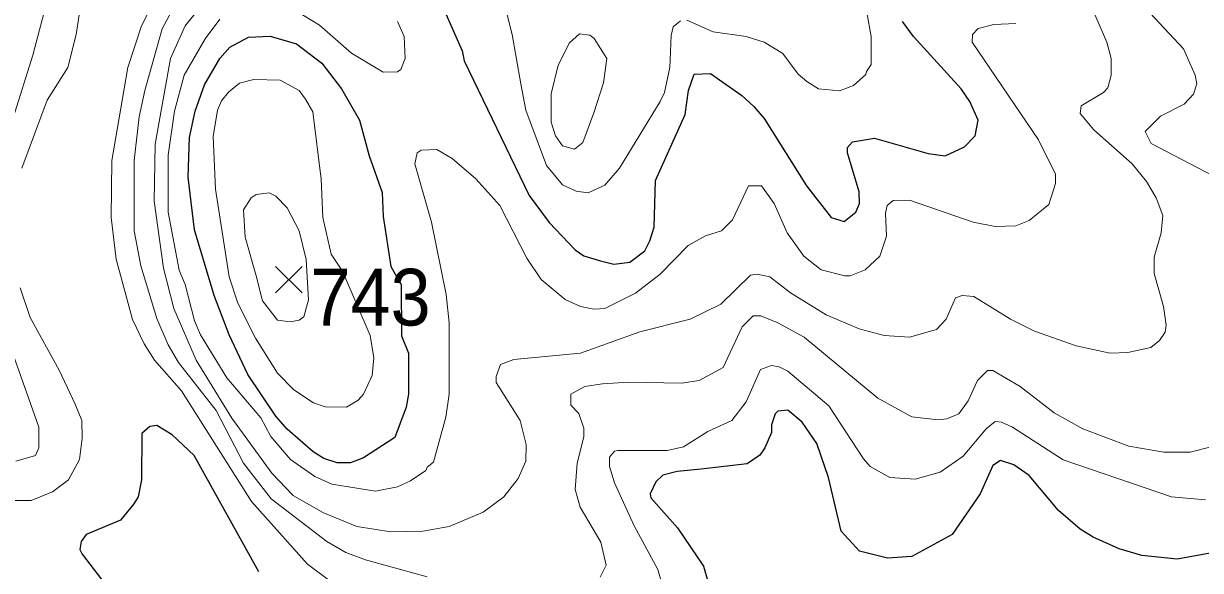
# Model space of a CAD drawing. Extents: x 423 to 448.8, y 7456.3 to 7484.
# Drawn here: x 438.652 to 440.312, y 7468.444 to 7469.215 of the extents above; entities that cross this region are included whole.
import ezdxf
from ezdxf.enums import TextEntityAlignment as Align

# ---------------------------------------------------------------- set-up
doc = ezdxf.new("R2010")
doc.units = 0
doc.header["$LTSCALE"] = 0.032
for name, color, linetype, lineweight in [('1', 7, 'Continuous', 25), ('2', 7, 'Continuous', 13), ('21', 7, 'Continuous', 25)]:
    doc.layers.add(name, color=color, linetype=linetype, lineweight=lineweight)
doc.layers.add('61', color=7, linetype='Continuous')

msp = doc.modelspace()

# ---------------------------------------------------------------- linework, layer by layer
at = {"layer": '1'}
for points in [[(439.2365, 7469.2538), (439.2705, 7469.1764), (439.2736, 7469.1625), (439.3649, 7468.9723), (439.3935, 7468.9343), (439.4299, 7468.8957), (439.4423, 7468.8872), (439.4659, 7468.8804), (439.4844, 7468.8756), (439.5071, 7468.8784), (439.5284, 7468.8945), (439.5355, 7468.9087), (439.5414, 7468.9277), (439.5432, 7468.9938), (439.5853, 7469.0867), (439.59, 7469.1208), (439.5977, 7469.1439), (439.6209, 7469.1447), (439.665, 7469.1138), (439.682, 7469.0983), (439.6967, 7469.0813), (439.7563, 7468.9862), (439.7911, 7468.9413), (439.8096, 7468.9359), (439.8259, 7468.949), (439.8313, 7468.9614), (439.8305, 7468.9776), (439.8143, 7469.0326), (439.8143, 7469.0403), (439.8213, 7469.048), (439.8522, 7469.0534), (439.928, 7469.0318), (439.952, 7469.0287), (439.979, 7469.0411), (439.9945, 7469.0565), (439.9984, 7469.0789), (439.9868, 7469.1053), (439.9744, 7469.1231), (439.9071, 7469.1966), (439.8916, 7469.2182)], [(440.3782, 7468.4772), (440.2792, 7468.4594), (440.2296, 7468.4648), (440.1972, 7468.4741), (440.1608, 7468.4904), (440.1422, 7468.502), (440.112, 7468.5283), (440.0703, 7468.5777), (440.0487, 7468.5925), (440.0301, 7468.5986), (440.0193, 7468.5917), (440.0014, 7468.5515), (439.962, 7468.4942), (439.9048, 7468.4633), (439.8708, 7468.461), (439.8313, 7468.471), (439.805, 7468.4989), (439.7872, 7468.5747), (439.771, 7468.6227), (439.7501, 7468.6528), (439.73, 7468.6698), (439.716, 7468.6682), (439.7122, 7468.6644), (439.7068, 7468.6489), (439.7068, 7468.6381), (439.6975, 7468.6165), (439.6905, 7468.6064), (439.6728, 7468.594), (439.6078, 7468.5863), (439.5738, 7468.5832), (439.5536, 7468.5778), (439.5436, 7468.5685), (439.5358, 7468.5515), (439.5366, 7468.5461)], [(438.9836, 7468.4417), (438.8923, 7468.6056), (438.8614, 7468.635), (438.8397, 7468.6481), (438.8297, 7468.6466), (438.8188, 7468.6366), (438.8181, 7468.5716), (438.8134, 7468.5476), (438.8072, 7468.5376), (438.7887, 7468.5143), (438.74, 7468.4942), (438.733, 7468.4842), (438.7314, 7468.4733), (438.7345, 7468.4664), (438.7732, 7468.4161)], [(439.5366, 7468.5461), (439.5745, 7468.5035), (439.6109, 7468.4494), (439.6202, 7468.4169)]]:
    msp.add_lwpolyline(points, dxfattribs=at)
msp.add_lwpolyline([(439.1392, 7469.0285), (439.1575, 7468.9768), (439.1589, 7468.9428), (439.17, 7468.8725), (439.1844, 7468.8468), (439.1851, 7468.7747), (439.195, 7468.7503), (439.1947, 7468.6923), (439.1917, 7468.6737), (439.1754, 7468.6311), (439.1313, 7468.6025), (439.1128, 7468.5956), (439.0942, 7468.5956), (439.0756, 7468.6017), (439.0602, 7468.611), (439.0238, 7468.6427), (439.0075, 7468.6613), (438.9681, 7468.7201), (438.9418, 7468.7758), (438.9209, 7468.8315), (438.8931, 7468.9243), (438.8838, 7468.9986), (438.8861, 7469.0542), (438.8938, 7469.0914), (438.907, 7469.1285), (438.9287, 7469.1656), (438.9426, 7469.1818), (438.9689, 7469.1958), (438.9998, 7469.1973), (439.037, 7469.1865), (439.0725, 7469.1594), (439.1004, 7469.1231), (439.1259, 7469.079)], close=True, dxfattribs=at)
at = {"layer": '2'}
for points in [[(438.6286, 7469.7906), (438.6804, 7469.6343), (438.6858, 7469.6111), (438.6982, 7469.5059), (438.7051, 7469.4688), (438.7353, 7469.3621), (438.7415, 7469.3157), (438.7384, 7469.2801), (438.726, 7469.1997), (438.7144, 7469.1532), (438.685, 7469.1068), (438.6494, 7469.0109)], [(438.6371, 7469.0821), (438.6649, 7469.1703), (438.6881, 7469.2584), (438.6974, 7469.3172), (438.6889, 7469.3745), (438.6843, 7469.4348), (438.6719, 7469.5075), (438.6441, 7469.5957)], [(439.1135, 7468.4068), (439.0524, 7468.4524), (438.9735, 7468.5407), (438.8745, 7468.6969), (438.8366, 7468.7402), (438.8219, 7468.7634), (438.8057, 7468.7975), (438.7825, 7468.8825), (438.7755, 7468.9413), (438.7763, 7469.0218), (438.7987, 7469.1532), (438.8181, 7469.212), (438.8366, 7469.2476), (438.8498, 7469.2832), (438.8591, 7469.3172), (438.8761, 7469.4255), (438.8761, 7469.4611), (438.8854, 7469.5183), (438.8885, 7469.5647)], [(439.5784, 7469.219), (439.5683, 7469.2105), (439.5652, 7469.1981), (439.5637, 7469.1532), (439.5559, 7469.1177), (439.5498, 7469.1053), (439.4925, 7469.0109), (439.4716, 7468.9869), (439.4485, 7468.9761), (439.4314, 7468.9784), (439.4121, 7468.9877), (439.3897, 7469.0148), (439.3603, 7469.0929), (439.3533, 7469.13), (439.3409, 7469.1997), (439.3231, 7469.2708)], [(440.2072, 7469.2662), (440.2884, 7469.1795), (440.3046, 7469.1424), (440.307, 7469.13), (440.3023, 7469.1153), (440.2892, 7469.1014), (440.2559, 7469.0844), (440.2343, 7469.0627), (440.2428, 7469.0457), (440.341, 7468.9947)], [(439.0795, 7468.4842), (439.0013, 7468.5445), (438.9619, 7468.5948), (438.9233, 7468.6691), (438.8706, 7468.7371), (438.8559, 7468.7619), (438.8397, 7468.799), (438.8173, 7468.8733), (438.808, 7468.9228), (438.808, 7469.0218), (438.815, 7469.0836), (438.8227, 7469.1208), (438.8474, 7469.2074), (438.8737, 7469.2569)], [(438.9062, 7469.2445), (438.8799, 7469.212), (438.8591, 7469.1656), (438.8374, 7469.045), (438.8359, 7468.9645), (438.849, 7468.8702), (438.8637, 7468.8129), (438.8745, 7468.7882), (438.8954, 7468.7402), (438.9457, 7468.6582), (439.0022, 7468.5809), (439.0323, 7468.5492), (439.0741, 7468.5252), (439.1221, 7468.5058), (439.17, 7468.4981), (439.2149, 7468.4989), (439.252, 7468.5058), (439.3, 7468.5259), (439.3293, 7468.5476), (439.3494, 7468.5731), (439.3603, 7468.5979), (439.361, 7468.6211), (439.3525, 7468.6551), (439.3185, 7468.7085), (439.3185, 7468.717), (439.3247, 7468.734), (439.3433, 7468.741), (439.4376, 7468.7502), (439.5212, 7468.7804), (439.5923, 7468.7982), (439.6356, 7468.8191), (439.6774, 7468.8601), (439.6867, 7468.8616), (439.7044, 7468.8578), (439.7338, 7468.8353), (439.7841, 7468.8044), (439.8305, 7468.7843), (439.8661, 7468.775), (439.9017, 7468.7727), (439.9396, 7468.7835)], [(439.1793, 7469.2182), (439.1885, 7469.1966), (439.1901, 7469.1656), (439.1839, 7469.1501), (439.1792, 7469.1471), (439.1591, 7469.1463), (439.1143, 7469.1733), (439.0694, 7469.2128), (439.0261, 7469.2391)], [(439.8414, 7469.2306), (439.8476, 7469.1966), (439.8476, 7469.1571), (439.841, 7469.1473), (439.8398, 7469.1432), (439.8228, 7469.1277), (439.8027, 7469.12), (439.7733, 7469.123), (439.757, 7469.1331), (439.7447, 7469.1439), (439.723, 7469.1726), (439.6967, 7469.1888), (439.6712, 7469.1966), (439.6248, 7469.2035), (439.5877, 7469.2197)], [(439.9396, 7468.7835), (439.9535, 7468.7982), (439.9667, 7468.8283), (439.9759, 7468.8314), (439.9922, 7468.8299), (440.044, 7468.7982), (440.0781, 7468.7812), (440.1368, 7468.7603), (440.1848, 7468.7502), (440.2095, 7468.751), (440.242, 7468.758), (440.2544, 7468.7681), (440.2621, 7468.7796), (440.2637, 7468.7897), (440.2598, 7468.816), (440.2467, 7468.8624), (440.2467, 7468.8856), (440.2567, 7468.9197), (440.259, 7468.9444), (440.2497, 7468.9692), (440.2358, 7468.9924), (440.2157, 7469.0171), (440.1616, 7469.065), (440.1422, 7469.0883), (440.1438, 7469.0991), (440.1755, 7469.1177), (440.1816, 7469.1246), (440.1863, 7469.1424), (440.1863, 7469.1656), (440.1801, 7469.1888), (440.16, 7469.2352)], [(438.9287, 7469.2213), (438.9078, 7469.1935), (438.8784, 7469.1424), (438.8645, 7469.0914), (438.856, 7469.0295), (438.856, 7468.9491), (438.8714, 7468.8671), (438.8799, 7468.847), (438.8931, 7468.7959), (438.9016, 7468.7758), (438.9387, 7468.7154), (438.9867, 7468.659), (439.0006, 7468.6327), (439.0285, 7468.6002), (439.0625, 7468.5762), (439.0865, 7468.5654), (439.1484, 7468.5553), (439.1793, 7468.5615), (439.1978, 7468.57), (439.2195, 7468.5847)], [(439.2195, 7468.5847), (439.221, 7468.5894), (439.2303, 7468.5963), (439.2473, 7468.6598), (439.252, 7468.6923), (439.252, 7468.7309), (439.252, 7468.7928), (439.2481, 7468.833), (439.2272, 7468.9351), (439.204, 7469.0171), (439.2071, 7469.0325), (439.2125, 7469.0364), (439.2349, 7469.0372), (439.2566, 7469.0248), (439.2899, 7468.9962), (439.3239, 7468.9583), (439.3618, 7468.8841), (439.3819, 7468.8539), (439.416, 7468.826), (439.4376, 7468.816), (439.4562, 7468.8121), (439.4717, 7468.8129), (439.515, 7468.8346), (439.5498, 7468.8616), (439.5892, 7468.9018), (439.614, 7468.9158), (439.6364, 7468.9227), (439.6518, 7468.9382), (439.6743, 7468.9861), (439.6928, 7468.9862), (439.7106, 7468.9614), (439.7292, 7468.9197), (439.7524, 7468.8871), (439.7771, 7468.8678), (439.8104, 7468.8593), (439.8181, 7468.8593), (439.839, 7468.8678), (439.8599, 7468.8871), (439.8692, 7468.915), (439.8676, 7468.9475), (439.87, 7468.9583), (439.8785, 7468.9653), (439.9017, 7468.9661), (439.9914, 7468.9351), (440.0224, 7468.9289), (440.0518, 7468.9297), (440.0703, 7468.9374), (440.0982, 7468.9598), (440.1074, 7468.9893), (440.1074, 7469.0024), (440.0835, 7469.0511), (439.9899, 7469.1888), (439.9906, 7469.1997), (439.9984, 7469.2081), (440.0208, 7469.2136), (440.0518, 7469.2151)], [(438.6471, 7468.8423), (438.6611, 7468.8005), (438.702, 7468.7263), (438.7245, 7468.6783), (438.7338, 7468.6551), (438.7345, 7468.6304), (438.7307, 7468.6002), (438.7152, 7468.5716), (438.6928, 7468.5546), (438.6626, 7468.5422), (438.6379, 7468.5422)], [(440.3271, 7468.618), (440.2977, 7468.6102), (440.2606, 7468.6102), (440.2111, 7468.6188), (440.1461, 7468.6435), (440.1059, 7468.6659), (440.0579, 7468.7031), (440.0193, 7468.7255), (440.0115, 7468.7255), (439.9976, 7468.7116), (439.9844, 7468.683), (439.9713, 7468.6644), (439.9543, 7468.6574), (439.9419, 7468.6559), (439.9048, 7468.6605), (439.8568, 7468.6868), (439.7532, 7468.7727), (439.7161, 7468.7928), (439.6921, 7468.8028), (439.6812, 7468.8028), (439.6658, 7468.7874), (439.6387, 7468.7301), (439.6047, 7468.7116), (439.5799, 7468.7077), (439.5057, 7468.7092), (439.4686, 7468.7069), (439.4438, 7468.7031), (439.4237, 7468.6922), (439.4237, 7468.6767), (439.4353, 7468.6652), (439.4423, 7468.6443), (439.4423, 7468.6319), (439.433, 7468.5948), (439.4299, 7468.5577), (439.4368, 7468.5329), (439.4662, 7468.4834), (439.4739, 7468.4509), (439.4654, 7468.4339)], [(438.641, 7468.5979), (438.6688, 7468.6056), (438.6734, 7468.6165), (438.6734, 7468.6459), (438.6371, 7468.748)], [(440.3194, 7468.543), (440.2714, 7468.5476), (440.1183, 7468.5994), (440.0471, 7468.6458), (440.0316, 7468.6528), (440.0224, 7468.6535), (440.0099, 7468.6435), (439.9775, 7468.6048), (439.945, 7468.5824), (439.9094, 7468.5723), (439.8739, 7468.5747), (439.846, 7468.5901), (439.8367, 7468.601), (439.788, 7468.676), (439.73, 7468.7247), (439.7176, 7468.7309), (439.7068, 7468.7325), (439.6913, 7468.727), (439.6712, 7468.6814), (439.6511, 7468.6551), (439.6171, 7468.6396), (439.583, 7468.618), (439.5598, 7468.6126), (439.4902, 7468.6126), (439.4855, 7468.6118), (439.4786, 7468.6033), (439.4786, 7468.5902), (439.4855, 7468.567), (439.5134, 7468.5066), (439.5467, 7468.4448), (439.5567, 7468.4107)], [(439.2211, 7468.4347), (439.1344, 7468.4587), (439.1066, 7468.4687), (439.0795, 7468.4842)]]:
    msp.add_lwpolyline(points, dxfattribs=at)
for points in [[(439.4565, 7469.089), (439.4701, 7469.1316), (439.4747, 7469.1656), (439.4569, 7469.1942), (439.4507, 7469.1989), (439.436, 7469.2004), (439.4222, 7469.188), (439.4059, 7469.1563), (439.3959, 7469.1161), (439.3959, 7469.0759), (439.402, 7469.0565), (439.4121, 7469.0426), (439.4291, 7469.038), (439.4407, 7469.0473)], [(439.0717, 7468.9955), (439.0601, 7469.0906), (439.0493, 7469.1084), (439.0408, 7469.1208), (439.0138, 7469.1354), (438.9766, 7469.1362), (438.9565, 7469.1308), (438.941, 7469.1184), (438.931, 7469.106), (438.9256, 7469.0929), (438.9194, 7469.0558), (438.9225, 7468.9815), (438.9418, 7468.8578), (438.9542, 7468.8207), (438.979, 7468.7712), (439.0099, 7468.7217), (439.0331, 7468.6984), (439.0609, 7468.6799), (439.0772, 7468.6745), (439.1073, 7468.6737), (439.1236, 7468.6837), (439.1313, 7468.6923), (439.1437, 7468.7186), (439.146, 7468.7433), (439.1406, 7468.775), (439.1016, 7468.8659), (439.0858, 7468.8899), (439.0741, 7468.9413)], [(438.9797, 7468.8593), (438.9642, 7468.9135), (438.9619, 7468.9521), (438.9728, 7468.9691), (438.9797, 7468.9738), (438.9983, 7468.9761), (439.0076, 7468.9714), (439.0238, 7468.9552), (439.0408, 7468.9228), (439.0504, 7468.8822), (439.0538, 7468.8253), (439.047, 7468.8013), (439.0408, 7468.7967), (439.0277, 7468.7944), (439.0099, 7468.7966), (438.989, 7468.8238)]]:
    msp.add_lwpolyline(points, close=True, dxfattribs=at)
at = {"layer": '21'}
for p, q in [((439.0071, 7468.8725), (439.0446, 7468.835)), ((439.0446, 7468.8725), (439.0071, 7468.835))]:
    msp.add_line(p, q, dxfattribs=at)

# ---------------------------------------------------------------- texts
at = {"layer": '61', "width": 0.95}
msp.add_text('743', height=0.08, dxfattribs=at).set_placement((439.1413, 7468.7891), align=Align.CENTER)

doc.saveas('drawing.dxf')
